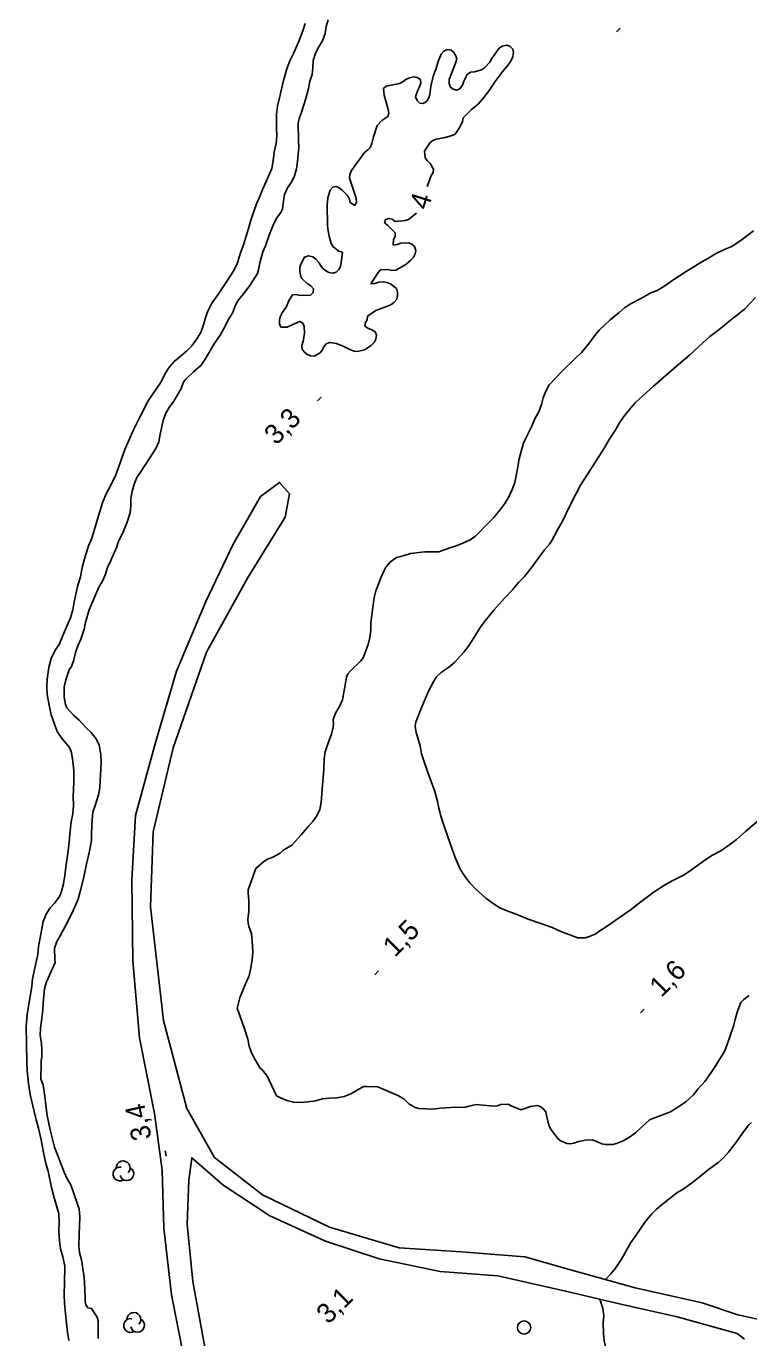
# Model space of a CAD drawing. Extents: x 381879 to 384696, y 5564785 to 5567594.
# Drawn here: x 382440.9 to 382550.2, y 5565741.1 to 5565939.6 of the extents above; entities that cross this region are included whole.
import ezdxf

# ---------------------------------------------------------------- set-up
doc = ezdxf.new("R2010")
doc.units = 0
for name, color, linetype in [('Niveau 2', 7, 'Continuous'), ('Niveau 22', 7, 'Continuous'), ('Niveau 3', 7, 'Continuous'), ('Niveau 36', 7, 'Continuous'), ('Niveau 4', 7, 'Continuous'), ('Niveau 44', 7, 'Continuous')]:
    doc.layers.add(name, color=color, linetype=linetype)

msp = doc.modelspace()

# ---------------------------------------------------------------- linework, layer by layer
at = {"layer": 'Niveau 2'}
for points in [[(382450.89, 5565819.52), (382451.02, 5565820.65), (382451.36, 5565821.65), (382451.84, 5565823.24), (382452.04, 5565824.3), (382452.12, 5565825.4), (382452.24, 5565828.15), (382452.19, 5565829.33), (382451.96, 5565830.84), (382451.48, 5565831.81), (382450.76, 5565832.68), (382450.02, 5565833.38), (382448.93, 5565834.58), (382448.14, 5565835.27), (382447.06, 5565836.44), (382446.87, 5565836.92), (382446.68, 5565838.02), (382446.65, 5565839.6), (382446.9, 5565840.65), (382447.44, 5565842.19), (382447.76, 5565842.67), (382448.13, 5565843.71), (382448.37, 5565844.81), (382448.72, 5565845.82), (382449.18, 5565846.84), (382449.68, 5565848.35), (382449.91, 5565849.34), (382450.42, 5565851.12), (382450.87, 5565852.24), (382451.9, 5565854.67), (382452.45, 5565855.62), (382452.91, 5565856.64), (382453.21, 5565857.68), (382453.73, 5565858.73), (382454.6, 5565860.68), (382454.96, 5565861.75), (382455.48, 5565862.81), (382456.17, 5565864.39), (382456.63, 5565865.92), (382456.73, 5565866.98), (382456.75, 5565868.1), (382456.96, 5565869.22), (382457.27, 5565870.29), (382457.68, 5565871.29), (382458.3, 5565872.26), (382459.55, 5565874.13), (382460.54, 5565875.7), (382461, 5565876.71), (382461.2, 5565877.87), (382461.65, 5565879.93), (382461.99, 5565880.92), (382462.57, 5565881.89), (382463.24, 5565882.85), (382464.32, 5565884.66), (382464.73, 5565885.7), (382465.09, 5565886.17), (382466.23, 5565887.26), (382467.4, 5565888.28), (382468.01, 5565889.21), (382469.38, 5565891.5), (382470.27, 5565892.82), (382470.79, 5565893.75), (382471.58, 5565895.3), (382472.16, 5565896.28), (382472.56, 5565897.25), (382473.05, 5565898.16), (382473.82, 5565899.08), (382474.74, 5565900.35), (382475.93, 5565902.18), (382476.09, 5565902.73), (382476.28, 5565903.77), (382476.73, 5565905.43), (382477.13, 5565906.36), (382477.69, 5565907.99), (382478.28, 5565909.5), (382478.8, 5565910.53), (382479.46, 5565911.41), (382479.7, 5565911.93), (382479.76, 5565912.45), (382480.02, 5565914.13), (382480.47, 5565915.13), (382481.06, 5565915.98), (382481.51, 5565916.93), (382481.79, 5565918.01), (382481.95, 5565919.14), (382482.19, 5565921.28), (382482.12, 5565922.31), (382482.06, 5565924.99), (382482.21, 5565925.56), (382482.58, 5565926.61), (382483.21, 5565928.63), (382483.63, 5565930.19), (382483.84, 5565931.3), (382484.16, 5565932.31), (382484.3, 5565933.32), (382484.35, 5565934.4), (382484.69, 5565935.51), (382485.18, 5565936.47), (382485.74, 5565937.4), (382486.13, 5565938.48), (382486.31, 5565939.57)], [(382486.31, 5565939.57), (382486.62, 5565940.56)], [(382482.36, 5565898.84), (382483.95, 5565898.87), (382484.36, 5565899.28), (382484.39, 5565899.85), (382484, 5565900.3), (382483.46, 5565900.59), (382482.63, 5565901.39), (382482.41, 5565901.93), (382482.31, 5565902.5), (382482.33, 5565903.06), (382482.47, 5565903.6), (382483.03, 5565904.65), (382483.64, 5565904.82), (382484.27, 5565904.69), (382484.75, 5565904.33), (382485.13, 5565903.89), (382485.77, 5565902.98), (382486.2, 5565902.62), (382486.73, 5565902.32), (382487.29, 5565902.2), (382487.81, 5565902.39), (382488.22, 5565902.77), (382488.48, 5565903.24), (382488.59, 5565903.83), (382488.75, 5565905.39), (382488.2, 5565905.56), (382487.38, 5565906.18), (382487.05, 5565906.71), (382486.74, 5565907.83), (382486.53, 5565908.95), (382486.51, 5565909.52), (382486.47, 5565912.49), (382486.55, 5565913.62), (382486.9, 5565914.76), (382487.29, 5565915.21), (382487.82, 5565915.32), (382488.29, 5565915.13), (382488.78, 5565914.74), (382489.56, 5565913.92), (382489.81, 5565913.41), (382489.92, 5565912.91), (382490.63, 5565912.47), (382490.89, 5565912.98), (382490.84, 5565913.55), (382490.62, 5565914.16), (382489.85, 5565916.6), (382489.88, 5565917.17), (382490.14, 5565917.74), (382490.77, 5565918.65), (382492.12, 5565920.49), (382492.63, 5565920.88), (382492.96, 5565921.26), (382493.19, 5565921.84), (382493.48, 5565922.84), (382494.04, 5565924.55), (382494.72, 5565925.32), (382495.63, 5565925.94), (382495.8, 5565926.42), (382495.67, 5565927), (382495.08, 5565929.17), (382494.98, 5565930.18), (382495.36, 5565930.54), (382495.89, 5565930.6), (382497.42, 5565930.91), (382497.92, 5565931.16), (382498.35, 5565931.55), (382498.93, 5565931.79), (382499.54, 5565931.91), (382500.08, 5565931.84), (382500.56, 5565931.52), (382500.62, 5565930.98), (382500.43, 5565930.4), (382500.18, 5565929.94), (382499.8, 5565928.92), (382500.05, 5565928.36), (382500.49, 5565927.97), (382501, 5565927.91), (382501.49, 5565928.21), (382501.82, 5565928.74), (382501.97, 5565929.28), (382502.15, 5565930.45), (382502.5, 5565932.02), (382502.95, 5565933.18), (382503.24, 5565934.27), (382503.71, 5565935.37), (382504.12, 5565935.83), (382504.61, 5565936.05), (382505.19, 5565935.96), (382505.61, 5565935.61), (382505.94, 5565935.12), (382506.05, 5565934.59), (382505.89, 5565934.01), (382505.59, 5565933.37), (382504.89, 5565931.52), (382504.91, 5565930.91), (382505.12, 5565930.39), (382505.51, 5565930.05), (382506.05, 5565929.9), (382506.5, 5565930.12), (382506.91, 5565930.67), (382507.13, 5565931.27)], [(382507.13, 5565931.27), (382507.64, 5565932.3), (382508.13, 5565932.66), (382508.72, 5565932.67), (382509.81, 5565933), (382510.23, 5565933.31), (382511.04, 5565934.15), (382511.37, 5565934.69), (382512.42, 5565936.23), (382512.95, 5565936.59), (382513.6, 5565936.72), (382514.11, 5565936.6), (382514.56, 5565936.14), (382514.65, 5565935.61), (382514.55, 5565935.02), (382514.28, 5565934.41), (382513.87, 5565933.79), (382512.91, 5565932.66), (382511.86, 5565931.25), (382511.07, 5565930.01), (382510.21, 5565928.88), (382509.28, 5565927.82), (382508.28, 5565926.99), (382507.03, 5565925.74), (382506.91, 5565925.14), (382506.44, 5565924.17), (382505.82, 5565923.26), (382505.23, 5565923.01), (382504.1, 5565922.72), (382502.94, 5565922.51), (382502.43, 5565922.28), (382501.99, 5565921.95), (382501.18, 5565920.67)], [(382501.18, 5565920.67), (382501.27, 5565919.69), (382501.59, 5565919.25), (382502.04, 5565918.83), (382502.56, 5565917.98), (382502.47, 5565917.47), (382502.21, 5565916.98), (382501.58, 5565915.32)], [(382499.98, 5565911.28), (382498.75, 5565910.32), (382498.24, 5565910.19), (382496.74, 5565910.05), (382496.31, 5565910.38), (382495.81, 5565910.5), (382495.28, 5565910.34), (382495.13, 5565909.84), (382495.58, 5565909.46), (382496.74, 5565908.34), (382496.73, 5565907.78), (382496.49, 5565907.33), (382496.45, 5565906.46), (382497.03, 5565906.56), (382497.6, 5565906.77), (382498.8, 5565906.83), (382499.26, 5565906.61), (382499.68, 5565906.23), (382499.86, 5565905.66), (382499.77, 5565905.13), (382499.53, 5565904.65), (382499.12, 5565904.19), (382498.34, 5565903.52), (382496.86, 5565902.65), (382496.24, 5565902.63), (382495.61, 5565902.75), (382494.5, 5565902.72), (382494.15, 5565902.3), (382493.06, 5565900.59), (382493.64, 5565900.65), (382494.25, 5565900.86), (382494.9, 5565900.93), (382495.5, 5565900.82), (382496.05, 5565900.6), (382496.95, 5565899.88), (382497.09, 5565899.29), (382497.11, 5565898.79), (382496.98, 5565898.28), (382496.56, 5565897.8), (382496.06, 5565897.42), (382495.45, 5565897.16), (382493.84, 5565896.57), (382492.57, 5565895.69), (382492.5, 5565895.16), (382492.24, 5565894.73), (382492.16, 5565894.2), (382492.7, 5565893.82), (382493.2, 5565893.66), (382493.7, 5565893.34), (382493.9, 5565892.85), (382493.83, 5565892.22), (382493.56, 5565891.73), (382493.13, 5565891.28), (382492.08, 5565890.6), (382491.03, 5565890.34), (382490.53, 5565890.4), (382489.99, 5565890.59), (382488.98, 5565891.13), (382487.89, 5565891.56), (382486.83, 5565891.71), (382486.32, 5565891.51), (382485.94, 5565891.07), (382485.72, 5565890.58), (382485.4, 5565890.18), (382484.47, 5565889.67), (382483.92, 5565889.71), (382483.37, 5565889.95), (382482.96, 5565890.3), (382482.65, 5565890.74), (382482.63, 5565891.28), (382482.83, 5565891.91), (382483.03, 5565893.07), (382482.97, 5565894.15), (382482.75, 5565894.63), (382482.31, 5565894.88), (382481.8, 5565894.7), (382480.38, 5565894.02), (382479.46, 5565894.07), (382479.26, 5565894.56), (382479.24, 5565895.13), (382479.35, 5565895.62), (382479.66, 5565896.19), (382480.24, 5565897.06), (382480.66, 5565898.05), (382481.22, 5565898.92), (382481.76, 5565898.97), (382482.36, 5565898.84)], [(382550.93, 5565908.61), (382549.06, 5565907.21), (382547.67, 5565906.25), (382546.67, 5565905.83), (382545.08, 5565905.1), (382544.15, 5565904.49), (382543.15, 5565903.92), (382540.76, 5565902.47), (382538.75, 5565901.16), (382537.36, 5565900.18), (382536.39, 5565899.6), (382535.42, 5565899.22), (382534, 5565898.43), (382532.45, 5565897.63), (382531.47, 5565897.03), (382530.62, 5565896.27), (382529.26, 5565895.13), (382527.62, 5565893.59), (382526.92, 5565892.76), (382525.97, 5565891.48), (382524.91, 5565890.22), (382524.01, 5565889.35), (382521.99, 5565887.39), (382520.02, 5565885.33), (382519.52, 5565884.37), (382519.15, 5565883.36), (382518.87, 5565882.33), (382518.48, 5565881.25), (382517.93, 5565880.27), (382517.31, 5565878.88), (382516.35, 5565876.96), (382516.15, 5565876.47), (382515.84, 5565875.44), (382515.45, 5565873.91), (382515.29, 5565872.88), (382514.83, 5565870.51), (382514.44, 5565869.47), (382513.92, 5565868.35), (382513.32, 5565867.36), (382512.71, 5565866.53), (382511.66, 5565865.26), (382510.87, 5565864.45), (382508.85, 5565862.37), (382507.96, 5565861.79), (382506.98, 5565861.33), (382505.89, 5565860.9), (382504.85, 5565860.59), (382503.36, 5565860.06), (382502.8, 5565860.04), (382501.22, 5565860.06), (382500.72, 5565860.01), (382499.05, 5565859.78), (382497.95, 5565859.46), (382496.94, 5565859.18), (382496.03, 5565858.54), (382495.34, 5565857.74), (382495.08, 5565857.23), (382494.64, 5565856.19), (382493.82, 5565854.13), (382493.56, 5565853.14), (382493.41, 5565852.02), (382493.07, 5565849.31)], [(382493.07, 5565849.31), (382493.05, 5565848.17), (382492.93, 5565847.06), (382492.66, 5565846.02), (382491.92, 5565843.98), (382491.54, 5565843.55), (382489.96, 5565842.03), (382489.59, 5565841.6), (382489.38, 5565841.08), (382489.29, 5565840.47), (382488.79, 5565837.66), (382488.31, 5565836.65), (382487.76, 5565835.72), (382487.36, 5565834.66), (382487.43, 5565834.06), (382487.37, 5565833.48), (382487.13, 5565832.45), (382486.7, 5565831.38), (382486.15, 5565829.76), (382486.02, 5565828.69), (382485.93, 5565827.07), (382485.75, 5565824.78), (382485.57, 5565822.09), (382485.33, 5565821.04), (382484.89, 5565820.09), (382484.26, 5565819.23), (382483.56, 5565818.46), (382482.55, 5565817.27), (382481.1, 5565815.65), (382480.23, 5565815.13), (382479.76, 5565814.84), (382479.35, 5565814.45), (382478.34, 5565813.89), (382477.31, 5565813.48), (382476.83, 5565813.13), (382475.64, 5565812.1), (382475.45, 5565811.58), (382474.52, 5565808.9), (382474.51, 5565808.36), (382474.58, 5565807.26), (382474.61, 5565805.6), (382474.46, 5565804.43), (382474.49, 5565803.82), (382474.61, 5565803.33), (382474.99, 5565802.25), (382475.13, 5565801.14), (382475.2, 5565799.44), (382475.1, 5565798.32), (382474.88, 5565796.78), (382474.58, 5565795.77), (382474.1, 5565794.67), (382473.23, 5565792.55), (382472.83, 5565790.94), (382473.02, 5565790.4), (382473.95, 5565787.86), (382474.46, 5565786.28), (382474.67, 5565785.24), (382475.03, 5565784.21), (382475.49, 5565783.27), (382476.32, 5565781.89), (382476.73, 5565781.53), (382477.43, 5565780.65), (382477.63, 5565780.19), (382478.8, 5565777.72), (382479.31, 5565777.44), (382480.33, 5565777.01), (382481.35, 5565776.73), (382482.48, 5565776.68), (382483.6, 5565776.77), (382484.71, 5565776.94), (382485.74, 5565777.24), (382486.77, 5565777.37), (382487.9, 5565777.4), (382489, 5565777.59), (382490.03, 5565778), (382490.98, 5565778.57), (382491.93, 5565779.11), (382492.47, 5565779.14), (382494.08, 5565779.07), (382494.58, 5565778.85), (382497.14, 5565777.75), (382498.07, 5565777.26), (382498.83, 5565776.5), (382499.75, 5565775.96), (382500.3, 5565775.81), (382501.4, 5565775.72), (382502.51, 5565775.71), (382503.56, 5565775.84), (382505.17, 5565775.94), (382507.4, 5565776.01), (382507.89, 5565776.16), (382508.97, 5565776.37), (382510.03, 5565776.31), (382511.69, 5565776.14), (382512.22, 5565776.2), (382512.73, 5565776.39), (382513.83, 5565776.43), (382514.3, 5565776.17), (382515.75, 5565775.57), (382516.24, 5565775.72), (382517.22, 5565776.11)], [(382451.79, 5565740.95), (382451.81, 5565743.66), (382451.64, 5565744.21), (382450.81, 5565745.52), (382450.27, 5565745.62), (382449.95, 5565746.06), (382449.83, 5565746.59), (382449.82, 5565747.13), (382449.74, 5565749.48), (382449.62, 5565750.58), (382449.3, 5565752.89), (382448.98, 5565753.98), (382448.89, 5565755.01), (382448.95, 5565756.7), (382449.06, 5565759.41), (382448.96, 5565760.57), (382448.59, 5565761.61), (382447.67, 5565764.23), (382447.14, 5565765.15), (382446.65, 5565766.15), (382446.25, 5565767.22), (382445.22, 5565769.93), (382444.93, 5565770.96), (382444.53, 5565772.57), (382444.07, 5565774.72), (382443.96, 5565775.89), (382443.75, 5565777.63), (382443.48, 5565779.31), (382443.16, 5565780.29), (382443.14, 5565780.87), (382443.2, 5565782), (382443.17, 5565783.06), (382443.27, 5565783.55), (382443.3, 5565784.59), (382443.23, 5565785.68), (382443.04, 5565786.84), (382443.08, 5565787.92), (382443.25, 5565789.03), (382443.45, 5565790.69), (382443.49, 5565791.78), (382443.68, 5565793.95), (382444, 5565794.96), (382444.87, 5565796.9), (382445.29, 5565797.89), (382445.24, 5565798.39), (382445.21, 5565800.05), (382445.58, 5565801.07), (382446.12, 5565802.03), (382447.11, 5565803.91), (382448.07, 5565805.84), (382448.77, 5565807.49), (382449.09, 5565808.62), (382449.66, 5565810.8), (382450, 5565812.57), (382450.48, 5565814.76), (382450.78, 5565816.37), (382450.8, 5565817.4), (382450.89, 5565819.52)], [(382517.22, 5565776.11), (382518.29, 5565776.23), (382518.79, 5565776.04), (382519.2, 5565775.71), (382519.52, 5565775.26), (382519.65, 5565774.69), (382520.03, 5565773.09), (382520.31, 5565772.66), (382521.28, 5565771.29), (382521.71, 5565770.94), (382522.71, 5565770.47), (382523.23, 5565770.43), (382523.78, 5565770.53), (382524.34, 5565770.74), (382525.42, 5565770.98), (382526.53, 5565771.04), (382527.02, 5565770.9), (382528.01, 5565770.42), (382528.59, 5565770.33), (382529.69, 5565770.32), (382530.21, 5565770.47), (382531.23, 5565770.89), (382532.18, 5565771.45), (382533.09, 5565772.08), (382533.93, 5565772.93), (382535.21, 5565774.08), (382535.74, 5565774.27), (382538.38, 5565775.29), (382539.35, 5565775.87), (382540.69, 5565776.78), (382541.87, 5565777.84), (382542.52, 5565778.72), (382543.59, 5565779.89), (382544.56, 5565781.21), (382545.14, 5565782.15), (382546.59, 5565784.51), (382547.02, 5565785.6), (382547.94, 5565788.25), (382548.16, 5565789.26), (382548.47, 5565790.35), (382549.04, 5565791.85), (382549.42, 5565792.24), (382550.24, 5565792.91)], [(382528.56, 5565749.89), (382529.37, 5565750.74), (382530.09, 5565751.62), (382530.97, 5565752.96), (382531.46, 5565753.89), (382532.41, 5565755.5), (382533.05, 5565756.41), (382534.57, 5565758.61), (382535.56, 5565759.85), (382536.29, 5565760.56), (382537.2, 5565761.31), (382539.36, 5565763.02), (382540.31, 5565763.58), (382541.58, 5565764.48), (382542.46, 5565765.21), (382544.15, 5565766.56), (382545.54, 5565767.58), (382546.4, 5565768.32), (382547.16, 5565769.2), (382548.23, 5565770.54), (382549.16, 5565771.9), (382550.18, 5565773.25), (382550.67, 5565773.68)], [(382529.19, 5565737.38), (382528.76, 5565738.84), (382528.37, 5565740.61), (382528.25, 5565741.75), (382528.23, 5565743.36), (382528.31, 5565744.41), (382528.13, 5565745.54), (382527.68, 5565746.93)]]:
    msp.add_lwpolyline(points, dxfattribs=at)
at = {"layer": 'Niveau 22'}
for points in [[(382465.64, 5565733.8), (382462.92, 5565747.58), (382461.76, 5565757.65), (382461.5, 5565766.45), (382460.32, 5565775.01), (382458.06, 5565786.49), (382457.04, 5565798.12), (382456.88, 5565810.38), (382457.46, 5565820.11), (382460.46, 5565831.16), (382463.65, 5565842), (382468.11, 5565852.5), (382472.2, 5565861.08), (382476.35, 5565868.4), (382479.25, 5565870.54), (382480.73, 5565868.8), (382480.08, 5565865.29), (382474.38, 5565856.08), (382468.2, 5565844.83), (382463.14, 5565830.37), (382460.14, 5565817.66), (382459.75, 5565806.3), (382461.71, 5565789.13), (382465.23, 5565775.79), (382469.39, 5565768.39), (382476.65, 5565762.73), (382486.81, 5565757.83), (382497.32, 5565754.7), (382506.76, 5565754.09), (382513.11, 5565753.59), (382516.38, 5565753.33)], [(382599.39, 5565772.37), (382600.34, 5565769.49), (382599.22, 5565766.37), (382597.41, 5565762.52), (382594.83, 5565756.41), (382592.22, 5565747.65), (382590.55, 5565744.28), (382588.78, 5565742.69), (382586.32, 5565741.62), (382583.52, 5565741.13), (382574.04, 5565741.53), (382561.98, 5565742.07), (382554.58, 5565743.24), (382548.57, 5565744.56)], [(382512.25, 5565750.47), (382503.57, 5565751.14), (382494.33, 5565753.03), (382486.18, 5565755.73), (382477.78, 5565759.55), (382470.68, 5565764.22), (382465.96, 5565768.33), (382465.54, 5565764.94), (382465.28, 5565758.29), (382466.13, 5565749.62), (382468.25, 5565738.01), (382472.63, 5565723.06)], [(382548.57, 5565744.56), (382543.18, 5565746.37), (382533.06, 5565748.63), (382523.27, 5565751.38), (382516.38, 5565753.33)], [(382549.58, 5565740.85), (382548.49, 5565741.73), (382539.42, 5565744.27), (382530.9, 5565746.17), (382522.52, 5565748.15), (382515.4, 5565749.77), (382512.25, 5565750.47)]]:
    msp.add_lwpolyline(points, dxfattribs=at)
at = {"layer": 'Niveau 3'}
for p, q in [((382530.2, 5565938.74), (382530.77, 5565939.31)), ((382484.98, 5565882.87), (382485.55, 5565883.44)), ((382493.66, 5565796.04), (382494.23, 5565796.61)), ((382533.83, 5565790.27), (382534.4, 5565790.84)), ((382462.09, 5565768.59), (382461.97, 5565769.38))]:
    msp.add_line(p, q, dxfattribs=at)
at = {"layer": 'Niveau 36'}
msp.add_circle((382516.24, 5565742.64), 1, dxfattribs=at)
at = {"layer": 'Niveau 4'}
for points in [[(382453.68, 5565870.04), (382454.5, 5565871.68), (382454.88, 5565872.82), (382455.83, 5565875.51), (382456.38, 5565876.79), (382457.16, 5565878.49), (382458.16, 5565880.54), (382459.35, 5565882.89), (382460.05, 5565883.86), (382461.36, 5565885.78), (382461.87, 5565886.83), (382462.44, 5565887.84), (382463.3, 5565888.84), (382463.88, 5565889.29), (382465.15, 5565890.42), (382465.96, 5565891.24), (382466.76, 5565892.26), (382467.33, 5565893.26), (382467.75, 5565894.38), (382468.04, 5565895.48), (382468.42, 5565896.47), (382469.01, 5565897.69), (382469.79, 5565898.77), (382471.24, 5565900.89), (382472.35, 5565902.63), (382472.89, 5565903.78), (382473.28, 5565905.12), (382473.79, 5565906.52), (382474.57, 5565908.97), (382474.91, 5565910.26), (382475.74, 5565912.72), (382476.24, 5565913.71), (382476.72, 5565915), (382477.29, 5565916.18), (382478.09, 5565918.05), (382478.28, 5565919.23), (382478.41, 5565920.51), (382478.73, 5565921.82), (382478.83, 5565923.01), (382478.77, 5565924.23), (382478.8, 5565926.27), (382478.96, 5565927.49), (382479.24, 5565928.76), (382479.85, 5565931.38), (382480.34, 5565933.14), (382480.8, 5565934.34), (382481.35, 5565935.48), (382482.1, 5565937.18), (382482.79, 5565938.9), (382483.11, 5565940.03)], [(382551.23, 5565898.54), (382549.59, 5565896.79), (382548.58, 5565895.94), (382547.49, 5565895.1), (382545.95, 5565893.85), (382544.36, 5565892.62), (382543.3, 5565891.67), (382541.27, 5565889.81), (382539.59, 5565888.38), (382537.34, 5565886.44), (382535.84, 5565885.09), (382534.19, 5565883.66), (382533.12, 5565882.66), (382532.41, 5565881.85), (382531.32, 5565880.53), (382530.68, 5565879.56), (382530.01, 5565878.41), (382529.2, 5565877.2), (382528.49, 5565875.96), (382527.73, 5565874.77), (382526.26, 5565872.41), (382524.8, 5565870.14), (382524.11, 5565868.88), (382523.22, 5565867.1), (382522.05, 5565864.69), (382521.24, 5565863.28), (382520.4, 5565861.64), (382520.09, 5565861.19), (382519.35, 5565860.34), (382518.61, 5565859.37), (382517.43, 5565857.74), (382516.31, 5565856.31), (382515.39, 5565855.38), (382514.52, 5565854.36), (382513.29, 5565853.03), (382511.69, 5565851.21), (382510.35, 5565849.6), (382509.6, 5565848.57), (382508.9, 5565847.42), (382507.91, 5565845.93), (382507.11, 5565844.85), (382505.74, 5565843.27), (382504.82, 5565842.55), (382503.76, 5565841.83), (382502.93, 5565841.09), (382502.57, 5565840.47), (382501.79, 5565838.96), (382501.35, 5565837.9), (382500.55, 5565836.08), (382499.85, 5565834.26), (382499.79, 5565833.65), (382499.9, 5565832.63), (382500.12, 5565832.03), (382500.51, 5565830.67), (382500.72, 5565829.45), (382501.16, 5565828.08), (382501.83, 5565826.24), (382502.73, 5565823.75), (382503.16, 5565822.27), (382503.35, 5565821.22), (382503.68, 5565819.9), (382504.07, 5565818.82), (382505.1, 5565815.76), (382505.81, 5565813.8), (382506.58, 5565812.01), (382507.24, 5565810.99), (382507.98, 5565810.01)], [(382447.39, 5565740.69), (382447.19, 5565741.91), (382446.99, 5565743.73), (382446.7, 5565746.29), (382446.68, 5565747.62), (382446.71, 5565749.36), (382446.77, 5565751.92), (382446.48, 5565753.32), (382446.11, 5565754.53), (382445.94, 5565755.78), (382445.87, 5565757.11), (382445.91, 5565758.53), (382445.87, 5565759.9), (382445.66, 5565760.55), (382445.09, 5565762.46), (382444.77, 5565763.81), (382444.23, 5565766.31), (382443.89, 5565767.45), (382443.53, 5565769.14), (382443.18, 5565771.03), (382442.8, 5565772.79), (382442.41, 5565774.05), (382442.11, 5565775.33), (382441.54, 5565777.9), (382441.25, 5565779.55), (382441.05, 5565781.48), (382441.02, 5565782.87), (382440.97, 5565785.63), (382440.93, 5565788.17), (382441.08, 5565790.03), (382441.28, 5565791.26), (382441.77, 5565794.23), (382441.88, 5565795.43), (382442.13, 5565796.57), (382442.67, 5565799.11), (382442.8, 5565800.3), (382443.05, 5565801.62), (382443.5, 5565804.11), (382443.94, 5565805.21), (382444.54, 5565806.15), (382445.27, 5565806.94), (382445.96, 5565807.86), (382446.21, 5565808.49), (382446.56, 5565809.77), (382446.77, 5565811.04), (382446.91, 5565812.34), (382447.18, 5565814.07), (382447.44, 5565816.01), (382447.54, 5565817.35), (382447.75, 5565819.17), (382447.96, 5565820.37), (382448.07, 5565821.64), (382448.04, 5565823.01), (382448.11, 5565825.17), (382448.12, 5565826.95), (382448, 5565828.29), (382447.79, 5565829.67), (382447.57, 5565830.23), (382447.29, 5565830.68), (382446.43, 5565831.7), (382445.65, 5565832.75), (382445.4, 5565833.4), (382444.72, 5565835.39), (382444.45, 5565836.6), (382444.11, 5565838.47), (382444.02, 5565839.63), (382444.09, 5565840.75), (382444.35, 5565842.52), (382444.68, 5565843.88), (382445.27, 5565845.08), (382445.94, 5565846.13), (382446.49, 5565847.4), (382447.61, 5565850.04), (382447.98, 5565851.25), (382448.18, 5565852.47), (382448.71, 5565855.02), (382449.12, 5565856.25), (382449.41, 5565857.69), (382449.74, 5565858.97), (382450.33, 5565860.94), (382450.87, 5565862.09), (382451.21, 5565863.28), (382451.99, 5565865.98), (382452.53, 5565867.61), (382453.06, 5565868.93), (382453.68, 5565870.04)], [(382507.98, 5565810.01), (382508.93, 5565809), (382510.45, 5565807.61), (382511.43, 5565806.91), (382512.58, 5565806.18), (382513.78, 5565805.65), (382515.02, 5565805.19), (382516.84, 5565804.46), (382518.8, 5565803.8), (382520.51, 5565803.17), (382521.82, 5565802.57), (382524.37, 5565801.63), (382525.5, 5565801.61), (382525.98, 5565801.76), (382527, 5565802.19), (382527.54, 5565802.56), (382528.97, 5565803.48), (382530.02, 5565804.23), (382532.27, 5565805.82), (382533.91, 5565807.09), (382535.91, 5565808.59), (382537.5, 5565809.61), (382538.64, 5565810.23), (382540.46, 5565811.16), (382541.58, 5565811.92), (382543.61, 5565813.38), (382544.77, 5565814.11), (382546.01, 5565814.81), (382547.38, 5565815.73), (382548.38, 5565816.52), (382549.72, 5565817.71), (382551.74, 5565819.44)]]:
    msp.add_lwpolyline(points, dxfattribs=at)
at = {"layer": 'Niveau 44'}
for centre, start_param, end_param in [((382455.1, 5565765.88), 1.88946, 5.776035), ((382455.59, 5565766.8), 6.029005, 9.968014), ((382456.14, 5565765.92), 3.902388, 7.872264), ((382457.21, 5565743.86), 6.029005, 9.968014), ((382456.72, 5565742.94), 1.88946, 5.776035), ((382457.76, 5565742.98), 3.902388, 7.872264)]:
    msp.add_ellipse(centre, major_axis=(0.912, -0.513), ratio=0.999925, start_param=start_param, end_param=end_param, dxfattribs=at)

# ---------------------------------------------------------------- texts
at = {"layer": 'Niveau 2'}
msp.add_text('4', height=3, rotation=72.7137, dxfattribs=at).set_placement((382501.7, 5565911.65))
at = {"layer": 'Niveau 3'}
for s, rotation, p in [('3,3', 44.7717, (382478.73, 5565876.06)), ('1,5', 44.7717, (382496.69, 5565798.58)), ('1,6', 44.7717, (382537.01, 5565792.51)), ('3,4', 102.2332, (382459.92, 5565771.29)), ('3,1', 44.7717, (382486.62, 5565743.01))]:
    msp.add_text(s, height=3, rotation=rotation, dxfattribs=at).set_placement(p)

doc.saveas('drawing.dxf')
